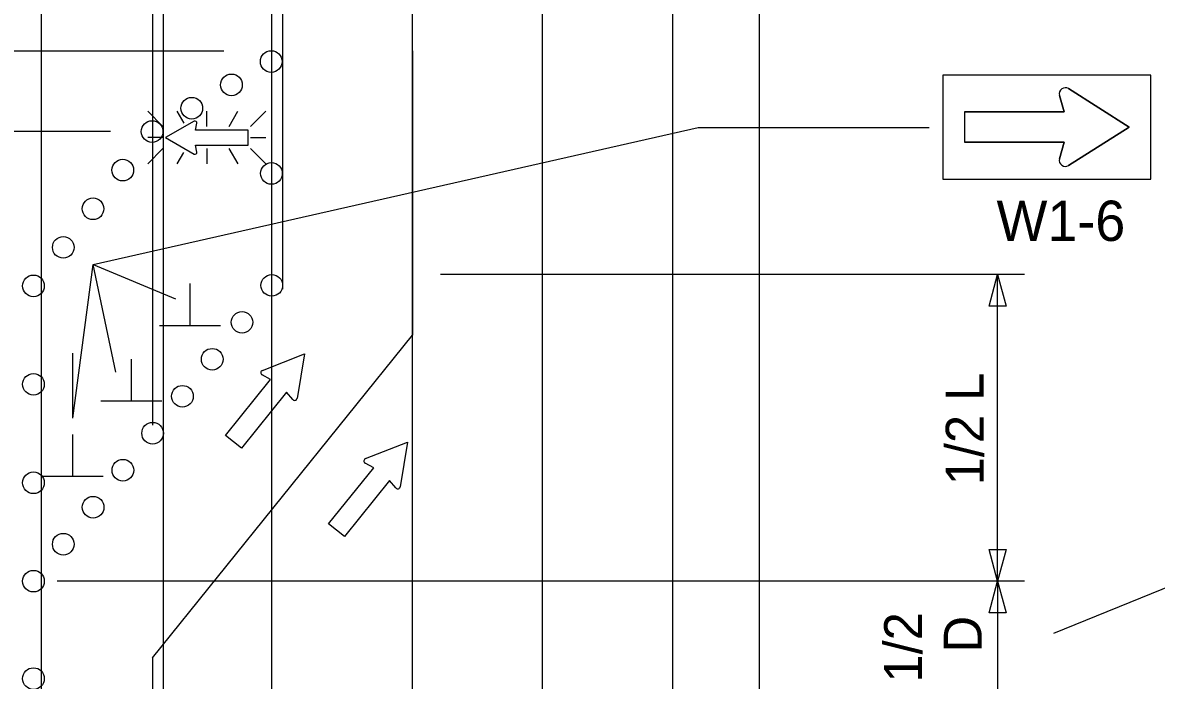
# Model space of a CAD drawing. Extents: x 16723 to 18475, y 7015 to 8267.
# Drawn here: x 17031.7 to 17241, y 7909.4 to 8030.8 of the extents above; entities that cross this region are included whole.
import ezdxf

# ---------------------------------------------------------------- set-up
doc = ezdxf.new("R2010")
doc.units = 0
for name, color, linetype in [('ALI_LEGAL_EX', 7, 'Continuous'), ('MT_SCRATCH_LEVEL_E', 7, 'Continuous'), ('PAVT_EDGE_EX', 7, 'Continuous'), ('TRAFFIC_SIGNS_PR', 7, 'Continuous'), ('TYPICAL_TEXT_DIMEN_PR', 7, 'Continuous')]:
    doc.layers.add(name, color=color, linetype=linetype)

msp = doc.modelspace()

# ---------------------------------------------------------------- linework, layer by layer
at = {"layer": 'ALI_LEGAL_EX'}
for p, q in [((17057.71, 7347.02), (17057.71, 8219.23)), ((17077.71, 7347.02), (17077.71, 8219.23)), ((17103.71, 7341.97), (17103.71, 8214.17)), ((17127.71, 7341.97), (17127.71, 8214.17))]:
    msp.add_line(p, q, dxfattribs=at)
at = {"layer": 'MT_SCRATCH_LEVEL_E'}
for p, q in [((17075.97, 7966.61), (17083.74, 7969.65)), ((17075.97, 7966.61), (17083.74, 7969.65)), ((17083.74, 7969.65), (17082.4, 7961.44)), ((17083.74, 7969.65), (17082.4, 7961.44)), ((17069.18, 7954.59), (17077.49, 7964.91)), ((17069.18, 7954.59), (17077.49, 7964.91)), ((17077.49, 7964.91), (17075.91, 7965.78)), ((17077.49, 7964.91), (17075.91, 7965.78)), ((17080.41, 7962.56), (17072.09, 7952.24)), ((17080.41, 7962.56), (17072.09, 7952.24)), ((17081.59, 7961.2), (17080.41, 7962.56)), ((17081.59, 7961.2), (17080.41, 7962.56)), ((17072.09, 7952.24), (17069.18, 7954.59)), ((17072.09, 7952.24), (17069.18, 7954.59)), ((17095, 7950.3), (17102.77, 7953.34)), ((17095, 7950.3), (17102.77, 7953.34)), ((17102.77, 7953.34), (17101.43, 7945.12)), ((17102.77, 7953.34), (17101.43, 7945.12)), ((17088.21, 7938.27), (17096.53, 7948.6)), ((17088.21, 7938.27), (17096.53, 7948.6)), ((17096.53, 7948.6), (17094.94, 7949.47)), ((17096.53, 7948.6), (17094.94, 7949.47)), ((17099.44, 7946.25), (17091.13, 7935.92)), ((17099.44, 7946.25), (17091.13, 7935.92)), ((17100.63, 7944.89), (17099.44, 7946.25)), ((17100.63, 7944.89), (17099.44, 7946.25)), ((17091.13, 7935.92), (17088.21, 7938.27)), ((17091.13, 7935.92), (17088.21, 7938.27))]:
    msp.add_line(p, q, dxfattribs=at)
for centre, start, end in [((17076.14, 7966.18), 111.3861, 241.123), ((17076.14, 7966.18), 111.3861, 241.123), ((17081.94, 7961.52), 221.1954, 350.7344), ((17081.94, 7961.52), 221.1954, 350.7344), ((17095.18, 7949.87), 111.3861, 241.123), ((17095.18, 7949.87), 111.3861, 241.123), ((17100.97, 7945.2), 221.1954, 350.7344), ((17100.97, 7945.2), 221.1954, 350.7344)]:
    msp.add_arc(centre, 0.463, start, end, dxfattribs=at)
at = {"layer": 'PAVT_EDGE_EX'}
for p, q in [((17035.15, 8267.39), (17035.15, 7438.21)), ((17055.71, 8214.17), (17055.71, 7956.5)), ((17079.71, 8214.17), (17079.71, 7981.61)), ((17151.71, 8214.17), (17151.71, 7352.81)), ((17167.71, 8214.17), (17167.71, 7352.81)), ((17103.71, 8025.65), (17103.71, 7973.14)), ((17055.71, 7913.53), (17103.71, 7973.14)), ((17055.71, 7913.53), (17055.71, 7743.81))]:
    msp.add_line(p, q, dxfattribs=at)
at = {"layer": 'TRAFFIC_SIGNS_PR'}
for p, q in [((17223.99, 8014.35), (17223.15, 8017.4)), ((17224.83, 8018.65), (17235.99, 8011.55)), ((17054.8, 8014.46), (17057.62, 8011.64)), ((17061.52, 8012.27), (17060.26, 8014.46)), ((17065.7, 8011.64), (17065.7, 8014.46)), ((17069.83, 8011.64), (17071.46, 8014.46)), ((17073.78, 8011.64), (17076.61, 8014.46)), ((17205.59, 8014.35), (17223.99, 8014.35)), ((17205.59, 8014.35), (17205.59, 8008.74)), ((17235.99, 8011.55), (17224.83, 8004.44)), ((17057.62, 8009.61), (17054.8, 8009.61)), ((17073.78, 8009.61), (17076.61, 8009.61)), ((17223.99, 8008.74), (17205.59, 8008.74)), ((17223.15, 8005.69), (17223.99, 8008.74)), ((17054.8, 8004.76), (17057.62, 8007.57)), ((17060.23, 8004.76), (17061.44, 8006.85)), ((17065.7, 8007.57), (17065.7, 8004.76)), ((17071.49, 8004.76), (17069.86, 8007.57)), ((17073.78, 8007.57), (17076.61, 8004.75))]:
    msp.add_line(p, q, dxfattribs=at)
msp.add_lwpolyline([(17201.59, 8001.95), (17239.99, 8001.95), (17239.99, 8021.15), (17201.59, 8021.15)], close=True, dxfattribs=at)
for points in [[(17223.15, 8017.4), (17223.99, 8014.35), (17205.59, 8014.35), (17205.59, 8008.74), (17223.99, 8008.74), (17223.15, 8005.69)], [(17224.83, 8004.44), (17235.99, 8011.55), (17224.83, 8018.65)], [(17063.37, 8012.62), (17058.06, 8009.61), (17063.37, 8006.57)], [(17063.87, 8006.93), (17063.64, 8008.22), (17073.37, 8008.22), (17073.37, 8010.97), (17063.64, 8010.97), (17063.88, 8012.27)]]:
    msp.add_lwpolyline(points, dxfattribs=at)
for centre in [(17077.6, 8023.65), (17077.6, 8023.65), (17070.27, 8019.34), (17062.94, 8015.03), (17055.61, 8010.72), (17050.19, 8003.59), (17077.65, 8002.98), (17044.7, 7996.46), (17039.21, 7989.33), (17033.71, 7982.21), (17033.71, 7982.21), (17033.71, 7982.21), (17033.71, 7982.21), (17033.71, 7982.21), (17077.71, 7982.31), (17072.21, 7975.48), (17066.71, 7968.65), (17033.71, 7964.03), (17061.21, 7961.82), (17055.71, 7954.99), (17050.21, 7948.16), (17033.71, 7945.85), (17044.71, 7941.33), (17039.21, 7934.5), (17033.71, 7927.67), (17033.71, 7909.67)]:
    msp.add_circle(centre, 2, dxfattribs=at)
for centre, radius, start, end in [((17224.23, 8017.7), 1.12, 57.5304, 195.3269), ((17224.23, 8017.7), 1.12, 57.5304, 195.3269), ((17063.54, 8012.32), 0.341, 350.7308, 118.8916), ((17063.54, 8006.87), 0.341, 241.4833, 9.9593), ((17224.23, 8005.39), 1.12, 164.6731, 302.4696), ((17224.23, 8005.39), 1.12, 164.6731, 302.4696)]:
    msp.add_arc(centre, radius, start, end, dxfattribs=at)
at = {"layer": 'TYPICAL_TEXT_DIMEN_PR'}
for p, q in [((16918.61, 8025.65), (17068.84, 8025.65)), ((17047.93, 8010.73), (16893.04, 8010.73)), ((17044.75, 7986.19), (17156.44, 8011.46)), ((17156.44, 8011.46), (17199.11, 8011.46)), ((17040.96, 7957.75), (17044.75, 7986.19)), ((17048.91, 7966.29), (17044.75, 7986.19)), ((17044.75, 7986.19), (17059.94, 7979.8)), ((17216.71, 7984.31), (17108.89, 7984.31)), ((17210.14, 7978.45), (17211.71, 7984.31)), ((17211.71, 7927.67), (17211.71, 7984.31)), ((17211.71, 7984.31), (17213.28, 7978.45)), ((17062.62, 7974.84), (17062.62, 7982.63)), ((17062.62, 7974.84), (17062.62, 7982.63)), ((17211.71, 7978.45), (17210.14, 7978.45)), ((17213.28, 7978.45), (17211.71, 7978.45)), ((17068.24, 7974.84), (17056.99, 7974.84)), ((17068.24, 7974.84), (17056.99, 7974.84)), ((17040.96, 7957.75), (17040.96, 7969.78)), ((17051.79, 7960.92), (17051.79, 7968.7)), ((17051.79, 7960.92), (17051.79, 7968.7)), ((17057.42, 7960.92), (17046.17, 7960.92)), ((17057.42, 7960.92), (17046.17, 7960.92)), ((17040.96, 7946.99), (17040.96, 7954.78)), ((17040.96, 7946.99), (17040.96, 7954.78)), ((17046.59, 7946.99), (17035.34, 7946.99)), ((17046.59, 7946.99), (17035.34, 7946.99)), ((17211.71, 7927.67), (17210.14, 7933.53)), ((17210.14, 7933.53), (17211.71, 7933.53)), ((17211.71, 7933.53), (17213.28, 7933.53)), ((17213.28, 7933.53), (17211.71, 7927.67)), ((17216.71, 7927.67), (17038.06, 7927.67)), ((17210.14, 7921.81), (17211.71, 7927.67)), ((17211.71, 7927.67), (17213.28, 7921.81)), ((17211.71, 7927.67), (17211.71, 7903.21)), ((17244.02, 7926.93), (17222.03, 7918)), ((17211.71, 7921.81), (17210.14, 7921.81)), ((17213.28, 7921.81), (17211.71, 7921.81))]:
    msp.add_line(p, q, dxfattribs=at)

# ---------------------------------------------------------------- texts
at = {"layer": 'TRAFFIC_SIGNS_PR'}
msp.add_text('W1-6', height=7.44, dxfattribs=at).set_placement((17211.53, 7990.51))
at = {"layer": 'TYPICAL_TEXT_DIMEN_PR'}
for s, p in [('1/2 L', (17209.15, 7945.37)), ('1/2', (17197.78, 7908.93)), ('D', (17208.78, 7914.5))]:
    msp.add_text(s, height=7, rotation=90, dxfattribs=at).set_placement(p)

doc.saveas('drawing.dxf')
